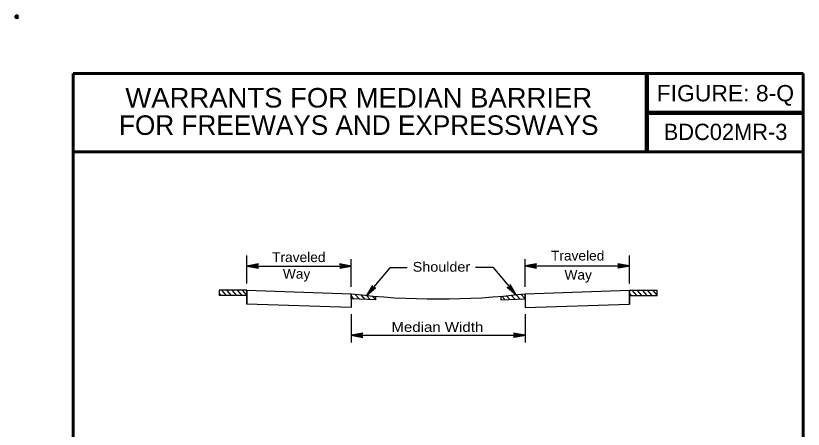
# Model space of a CAD drawing. Extents: x 58.027 to 58.702, y 1.635 to 2.519.
# Drawn here: x 58.027 to 58.656, y 2.189 to 2.519 of the extents above; entities that cross this region are included whole.
import ezdxf
from ezdxf.enums import TextEntityAlignment as Align

# ---------------------------------------------------------------- set-up
doc = ezdxf.new("R2010")
doc.units = 0
doc.header["$LTSCALE"] = 0.0031
doc.header["$PDMODE"] = 32
doc.header["$PDSIZE"] = 0.00155
for name, color, linetype, lineweight in [('1', 7, 'Continuous', 60), ('24', 7, 'Continuous', 25), ('5', 7, 'Continuous', 25)]:
    doc.layers.add(name, color=color, linetype=linetype, lineweight=lineweight)

msp = doc.modelspace()

# ---------------------------------------------------------------- linework, layer by layer
at = {"layer": '1'}
for p, q in [((58.072608, 2.472933), (58.655883, 2.472933)), ((58.072608, 1.68135), (58.072608, 2.472933)), ((58.072608, 2.410442), (58.655883, 2.410442))]:
    msp.add_line(p, q, dxfattribs=at)
at = {"layer": '1', "lineweight": 90}
for p, q in [((58.530892, 2.472933), (58.530892, 2.410442)), ((58.530892, 2.441683), (58.655883, 2.441683))]:
    msp.add_line(p, q, dxfattribs=at)
at = {"layer": '1', "lineweight": 25}
for p, q in [((58.31425, 2.294933), (58.31425, 2.292158)), ((58.414242, 2.294933), (58.414242, 2.292158))]:
    msp.add_line(p, q, dxfattribs=at)
at = {"layer": '1'}
msp.add_lwpolyline([(58.655883, 2.472933), (58.655883, 1.68135), (58.072608, 1.68135)], dxfattribs=at)
msp.add_point((58.027608, 2.518433), dxfattribs=at)
at = {"layer": '24'}
for p, q in [((58.211483, 2.305208), (58.211483, 2.3275)), ((58.517008, 2.305208), (58.517008, 2.3275)), ((58.294808, 2.302467), (58.294808, 2.324717)), ((58.433683, 2.302467), (58.433683, 2.324717)), ((58.211483, 2.319133), (58.294808, 2.319133)), ((58.433683, 2.31915), (58.517008, 2.31915)), ((58.294808, 2.280508), (58.294808, 2.258058)), ((58.433683, 2.280508), (58.433683, 2.258058)), ((58.294808, 2.263725), (58.433683, 2.263725))]:
    msp.add_line(p, q, dxfattribs=at)
for points in [[(58.211483, 2.319133), (58.220717, 2.3175), (58.218517, 2.319133), (58.220675, 2.320742), (58.211483, 2.319133), (58.212092, 2.31915), (58.220458, 2.317617), (58.218342, 2.31915), (58.2203, 2.320608), (58.212425, 2.319175), (58.212733, 2.319133), (58.2199, 2.317858), (58.218292, 2.31915), (58.21995, 2.320408), (58.212875, 2.319133), (58.213183, 2.319175), (58.21945, 2.31805), (58.218225, 2.319133), (58.219475, 2.320258), (58.214075, 2.319175), (58.214592, 2.319175), (58.218983, 2.318283), (58.218125, 2.319108), (58.21905, 2.320025), (58.214683, 2.319133), (58.215183, 2.3191), (58.218483, 2.318542), (58.217842, 2.319175), (58.218533, 2.319808), (58.215633, 2.319133), (58.2161, 2.319083), (58.218083, 2.318708), (58.21775, 2.31915), (58.218292, 2.319642), (58.216342, 2.319133), (58.217633, 2.318825), (58.21745, 2.319175), (58.218017, 2.319533), (58.216667, 2.319175), (58.217517, 2.318967), (58.217158, 2.319242), (58.217567, 2.319408), (58.217158, 2.31915), (58.217375, 2.319108)], [(58.294808, 2.319133), (58.285567, 2.320767), (58.287775, 2.319133), (58.285617, 2.317525), (58.294808, 2.319133), (58.294192, 2.319117), (58.285825, 2.320642), (58.28795, 2.319108), (58.285992, 2.31765), (58.293858, 2.319083), (58.29355, 2.319133), (58.286383, 2.320408), (58.287992, 2.319117), (58.286342, 2.317858), (58.293417, 2.319133), (58.293108, 2.319083), (58.286842, 2.320217), (58.288058, 2.319133), (58.286817, 2.318008), (58.292217, 2.319083), (58.291692, 2.319083), (58.287308, 2.319983), (58.288158, 2.319158), (58.287242, 2.318242), (58.2916, 2.319133), (58.291108, 2.319158), (58.287808, 2.319725), (58.288442, 2.319083), (58.287758, 2.31845), (58.29065, 2.319133), (58.290183, 2.319175), (58.288208, 2.319558), (58.288533, 2.319108), (58.287992, 2.318617), (58.28995, 2.319133), (58.288658, 2.319442), (58.288842, 2.319083), (58.288275, 2.318733), (58.289625, 2.319083), (58.288775, 2.3193), (58.289125, 2.319017), (58.288725, 2.31885), (58.289125, 2.319108), (58.288917, 2.319158)], [(58.339408, 2.317567), (58.325517, 2.317567), (58.306992, 2.295608)], [(58.394092, 2.318083), (58.407983, 2.318083), (58.426508, 2.296125)], [(58.433683, 2.31915), (58.442917, 2.317517), (58.440717, 2.31915), (58.442875, 2.320758), (58.433683, 2.31915), (58.434292, 2.319167), (58.442658, 2.317633), (58.440542, 2.319167), (58.4425, 2.320625), (58.434625, 2.319192), (58.434933, 2.31915), (58.4421, 2.317875), (58.440492, 2.319167), (58.44215, 2.320425), (58.435075, 2.31915), (58.435383, 2.319192), (58.44165, 2.318067), (58.440425, 2.31915), (58.441675, 2.320275), (58.436275, 2.319192), (58.436792, 2.319192), (58.441183, 2.318292), (58.440325, 2.319125), (58.44125, 2.320042), (58.436883, 2.31915), (58.437383, 2.319117), (58.440683, 2.318558), (58.440042, 2.319192), (58.440733, 2.319825), (58.437833, 2.31915), (58.4383, 2.3191), (58.440283, 2.318725), (58.439958, 2.319167), (58.440492, 2.319658), (58.438542, 2.31915), (58.439833, 2.318842), (58.43965, 2.319192), (58.440217, 2.31955), (58.438867, 2.319192), (58.439717, 2.318983), (58.439358, 2.319258), (58.439767, 2.319425), (58.439358, 2.319167), (58.439575, 2.319125)], [(58.517008, 2.31915), (58.507767, 2.320783), (58.509975, 2.31915), (58.507817, 2.317542), (58.517008, 2.31915), (58.516392, 2.319133), (58.508025, 2.320658), (58.51015, 2.319125), (58.508192, 2.317667), (58.516058, 2.3191), (58.51575, 2.31915), (58.508583, 2.320425), (58.510192, 2.319125), (58.508542, 2.317875), (58.515617, 2.31915), (58.515308, 2.3191), (58.509042, 2.320233), (58.510258, 2.31915), (58.509017, 2.318025), (58.514417, 2.3191), (58.513892, 2.3191), (58.509508, 2.32), (58.510358, 2.319175), (58.509442, 2.318258), (58.5138, 2.31915), (58.513308, 2.319175), (58.510008, 2.319742), (58.510642, 2.3191), (58.509958, 2.318467), (58.51285, 2.31915), (58.512383, 2.319192), (58.510408, 2.319575), (58.510733, 2.319125), (58.510192, 2.318633), (58.512142, 2.31915), (58.510858, 2.319458), (58.511042, 2.3191), (58.510475, 2.31875), (58.511817, 2.3191), (58.510975, 2.319317), (58.511325, 2.319033), (58.510925, 2.318867), (58.511325, 2.319125), (58.511117, 2.319175)], [(58.306992, 2.295608), (58.314192, 2.301617), (58.311525, 2.300983), (58.311692, 2.303667), (58.306992, 2.295608), (58.307367, 2.296083), (58.313933, 2.301492), (58.3114, 2.300858), (58.311542, 2.3033), (58.307567, 2.296358), (58.3078, 2.296567), (58.313392, 2.301217), (58.311367, 2.300825), (58.311475, 2.3029), (58.307883, 2.296675), (58.30805, 2.296933), (58.312958, 2.300992), (58.311342, 2.300758), (58.311283, 2.302442), (58.308625, 2.297617), (58.308958, 2.298017), (58.312475, 2.300792), (58.311292, 2.300667), (58.311183, 2.301967), (58.309058, 2.298058), (58.3094, 2.298417), (58.311958, 2.300575), (58.311058, 2.3005), (58.311017, 2.301433), (58.309667, 2.298783), (58.31, 2.299108), (58.311567, 2.300375), (58.311017, 2.300417), (58.310992, 2.301142), (58.310125, 2.299317), (58.311192, 2.300108), (58.3108, 2.300192), (58.310892, 2.300858), (58.3103, 2.2996), (58.311008, 2.300108), (58.310567, 2.300017), (58.3107, 2.300442), (58.310633, 2.299958), (58.310808, 2.300092)], [(58.426508, 2.296125), (58.4218, 2.304242), (58.421975, 2.3015), (58.419358, 2.302117), (58.426508, 2.296125), (58.4261, 2.296583), (58.421875, 2.303967), (58.422075, 2.301358), (58.419692, 2.301908), (58.425867, 2.296817), (58.425708, 2.297083), (58.422058, 2.303383), (58.422108, 2.301317), (58.420075, 2.301775), (58.425617, 2.297192), (58.425383, 2.297392), (58.4222, 2.302908), (58.422158, 2.301283), (58.4205, 2.301508), (58.424808, 2.298075), (58.424467, 2.298475), (58.422325, 2.302408), (58.422242, 2.301225), (58.42095, 2.301333), (58.424442, 2.298575), (58.42415, 2.298975), (58.42245, 2.301858), (58.422375, 2.300958), (58.421442, 2.301075), (58.423833, 2.2993), (58.423567, 2.299683), (58.422583, 2.301442), (58.42245, 2.300908), (58.421725, 2.301), (58.423375, 2.299842), (58.422775, 2.301025), (58.422633, 2.300658), (58.421992, 2.300858), (58.423133, 2.300058), (58.42275, 2.300842), (58.422767, 2.300392), (58.422375, 2.300592), (58.422833, 2.30045), (58.422733, 2.300642)], [(58.294808, 2.263725), (58.304042, 2.262092), (58.301842, 2.263725), (58.304, 2.265333), (58.294808, 2.263725), (58.295417, 2.263742), (58.303783, 2.262217), (58.301667, 2.26375), (58.303625, 2.265208), (58.29575, 2.263775), (58.296058, 2.263725), (58.303225, 2.26245), (58.301617, 2.26375), (58.303275, 2.265), (58.2962, 2.263725), (58.296508, 2.263775), (58.302775, 2.262642), (58.30155, 2.263725), (58.3028, 2.264858), (58.2974, 2.263775), (58.297917, 2.263775), (58.302308, 2.262875), (58.30145, 2.2637), (58.302375, 2.264617), (58.298008, 2.263725), (58.298508, 2.2637), (58.301808, 2.263133), (58.301167, 2.263775), (58.301858, 2.264408), (58.298958, 2.263725), (58.299425, 2.263683), (58.301408, 2.2633), (58.301083, 2.26375), (58.301617, 2.264242), (58.299667, 2.263725), (58.300958, 2.263417), (58.300775, 2.263775), (58.301342, 2.264125), (58.299992, 2.263775), (58.300842, 2.263558), (58.300483, 2.263842), (58.300892, 2.264008), (58.300483, 2.26375), (58.3007, 2.2637)], [(58.433683, 2.263725), (58.424442, 2.265358), (58.42665, 2.263725), (58.424492, 2.262117), (58.433683, 2.263725), (58.433067, 2.263708), (58.4247, 2.265242), (58.426825, 2.263708), (58.424867, 2.26225), (58.432733, 2.263683), (58.432425, 2.263725), (58.425258, 2.265), (58.426867, 2.263708), (58.425217, 2.262458), (58.432292, 2.263725), (58.431983, 2.263683), (58.425717, 2.264817), (58.426933, 2.263725), (58.425692, 2.2626), (58.431092, 2.263683), (58.430567, 2.263683), (58.426183, 2.264583), (58.427033, 2.26375), (58.426117, 2.262833), (58.430475, 2.263725), (58.429983, 2.263758), (58.426683, 2.264325), (58.427317, 2.263683), (58.426633, 2.26305), (58.429525, 2.263725), (58.429058, 2.263775), (58.427083, 2.26415), (58.427408, 2.263708), (58.426867, 2.263217), (58.428825, 2.263725), (58.427533, 2.264033), (58.427717, 2.263683), (58.42715, 2.263325), (58.4285, 2.263683), (58.42765, 2.263892), (58.428, 2.263617), (58.4276, 2.26345), (58.428, 2.263708), (58.427792, 2.26375)]]:
    msp.add_lwpolyline(points, dxfattribs=at)
at = {"layer": '5'}
for p, q in [((58.189258, 2.299725), (58.189258, 2.295558)), ((58.189258, 2.2971), (58.19065, 2.295558)), ((58.191083, 2.299725), (58.194817, 2.295558)), ((58.195242, 2.299725), (58.198983, 2.295558)), ((58.199408, 2.299725), (58.20315, 2.295558)), ((58.203575, 2.299725), (58.207317, 2.295558)), ((58.207742, 2.299725), (58.211483, 2.295558)), ((58.211483, 2.299725), (58.211483, 2.288608)), ((58.211483, 2.299725), (58.294808, 2.296942)), ((58.297767, 2.296592), (58.301383, 2.292567)), ((58.3024, 2.296083), (58.305667, 2.292433)), ((58.426508, 2.296125), (58.429633, 2.29265)), ((58.4303, 2.29655), (58.433683, 2.292775)), ((58.433683, 2.296942), (58.517008, 2.299725)), ((58.517008, 2.299725), (58.517008, 2.288608)), ((58.517008, 2.299725), (58.539225, 2.299725)), ((58.517008, 2.2971), (58.518392, 2.295558)), ((58.518825, 2.299725), (58.522558, 2.295558)), ((58.522992, 2.299725), (58.526725, 2.295558)), ((58.527158, 2.299725), (58.530892, 2.295558)), ((58.531325, 2.299725), (58.535058, 2.295558)), ((58.535492, 2.299725), (58.539225, 2.295558)), ((58.539225, 2.295558), (58.539225, 2.299725)), ((58.211483, 2.295558), (58.189258, 2.295558)), ((58.294808, 2.29525), (58.297092, 2.292708)), ((58.306992, 2.295608), (58.309958, 2.292292)), ((58.311542, 2.295175), (58.31425, 2.292158)), ((58.415025, 2.295), (58.417483, 2.292258)), ((58.418875, 2.29535), (58.421533, 2.292392)), ((58.4227, 2.295725), (58.425583, 2.292517)), ((58.517008, 2.295558), (58.539225, 2.295558))]:
    msp.add_line(p, q, dxfattribs=at)
for points in [[(58.294808, 2.296942), (58.294808, 2.285833), (58.211483, 2.288608), (58.211483, 2.299725), (58.189258, 2.299725)], [(58.31425, 2.294933), (58.31425, 2.292158), (58.294808, 2.292775), (58.294808, 2.296942)], [(58.414242, 2.294933), (58.414242, 2.292158), (58.433683, 2.292775), (58.433683, 2.296942)], [(58.433683, 2.296942), (58.433683, 2.285833), (58.517008, 2.288608), (58.517008, 2.299725)]]:
    msp.add_lwpolyline(points, dxfattribs=at)
msp.add_arc((58.364244, 2.873507), 0.580729, 263.13274, 276.86726, dxfattribs=at)

# ---------------------------------------------------------------- texts
at = {"layer": '1'}
for s, height, width, p in [('WARRANTS FOR MEDIAN BARRIER', 0.01562, 1.05, (58.300821, 2.445817)), ('FIGURE: 8-Q', 0.01303, 1.05, (58.593671, 2.450792)), ('Traveled', 0.0078, 1.05, (58.252938, 2.322275)), ('Traveled', 0.0078, 1.05, (58.475687, 2.323525)), ('Shoulder', 0.0078, 1.1, (58.366879, 2.314575)), ('Way', 0.0078, 1.05, (58.251158, 2.309017)), ('Way', 0.0078, 1.05, (58.476108, 2.308217)), ('Median Width', 0.0078, 1.15, (58.363608, 2.266458))]:
    msp.add_text(s, height=height, dxfattribs=dict(at, width=width)).set_placement(p, align=Align.CENTER)
for s, height, p in [('FOR FREEWAYS AND EXPRESSWAYS', 0.01562, (58.300812, 2.423942)), ('BDC02MR-3', 0.01303, (58.593821, 2.419858))]:
    msp.add_text(s, height=height, dxfattribs=at).set_placement(p, align=Align.CENTER)

doc.saveas('drawing.dxf')
